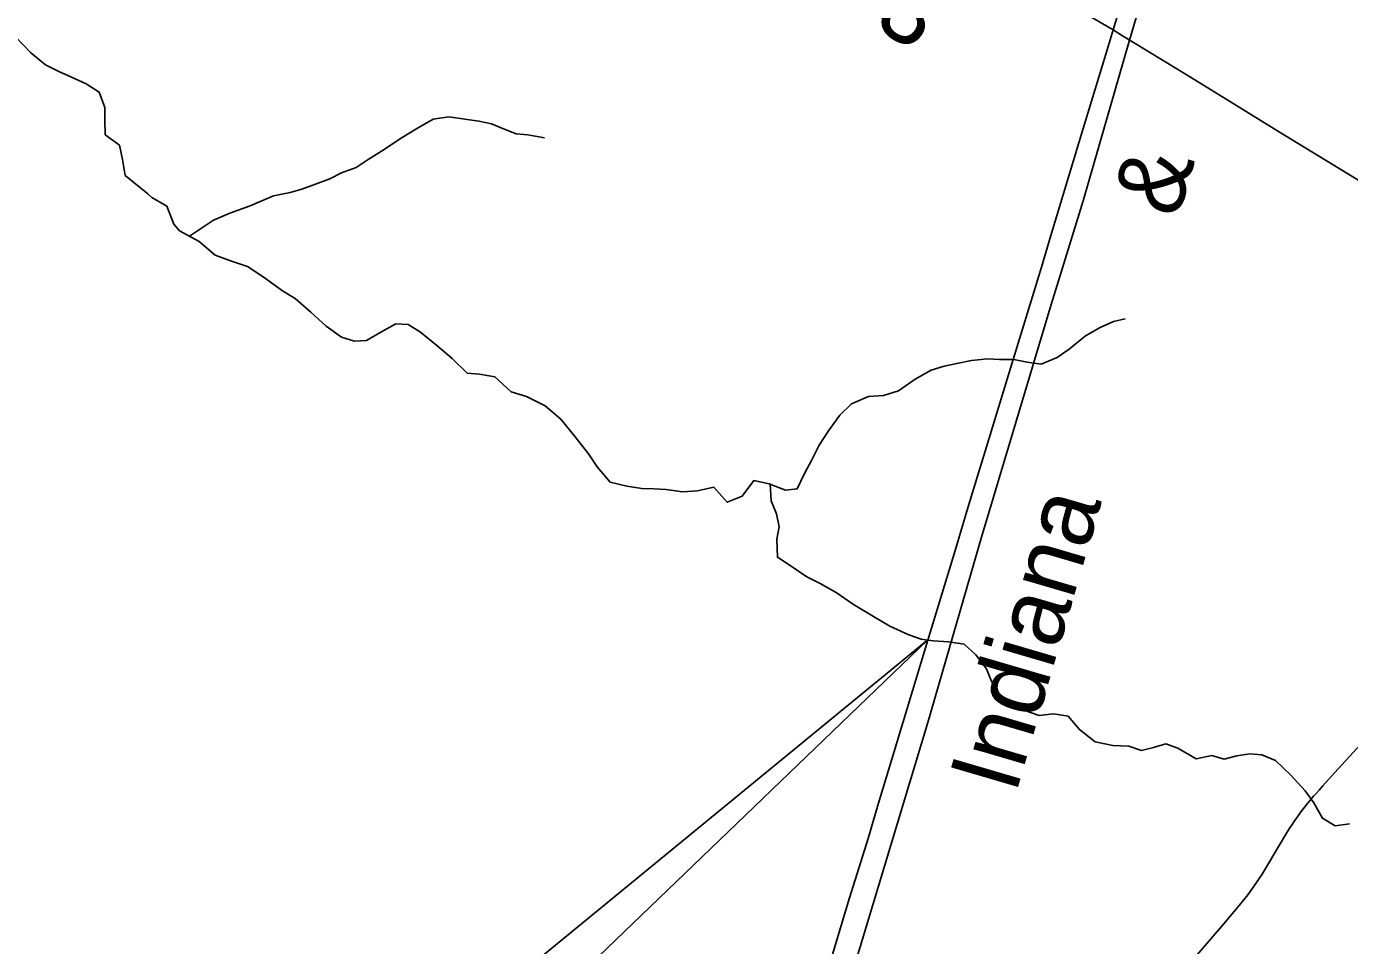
# Model space of a CAD drawing. Extents: x 0 to 34, y 0 to 22.
# Drawn here: x 4.817 to 5.891, y 17.368 to 18.113 of the extents above; entities that cross this region are included whole.
import ezdxf

# ---------------------------------------------------------------- set-up
doc = ezdxf.new("R2010")
doc.units = 0
for name, color, linetype in [('GM_X_County_Road', 7, 'Continuous'), ('GM_X_Minor_River', 7, 'Continuous'), ('GM_X_Rail_Line', 7, 'Continuous'), ('GM_X_Rail_Line_Text', 7, 'Continuous'), ('GM_X_Township_Road', 7, 'Continuous'), ('GM_X_Township_Road_Text', 7, 'Continuous'), ('GM_X_US_Route', 7, 'Continuous'), ('SH_Text', 7, 'Continuous')]:
    doc.layers.add(name, color=color, linetype=linetype)

msp = doc.modelspace()

# ---------------------------------------------------------------- linework, layer by layer
at = {"layer": 'GM_X_County_Road'}
msp.add_lwpolyline([(5.7466, 17.3365), (5.7884, 17.3849), (5.8012, 17.4001), (5.8081, 17.4089), (5.8114, 17.4135), (5.8146, 17.4179), (5.8172, 17.422), (5.8197, 17.4257), (5.8387, 17.4576), (5.8404, 17.4603), (5.8422, 17.4631), (5.8441, 17.466), (5.8455, 17.4681), (5.8475, 17.471), (5.8494, 17.4736), (5.8512, 17.4762), (5.8534, 17.479), (5.8562, 17.4826), (5.8591, 17.486), (5.8615, 17.4888), (5.8635, 17.4911), (5.866, 17.4938), (5.869, 17.4972), (5.8785, 17.5077), (5.9061, 17.5379)], dxfattribs=at)
at = {"layer": 'GM_X_Minor_River'}
for points in [[(4.8023, 18.111), (4.8205, 18.092), (4.8324, 18.0823), (4.8433, 18.0768), (4.8534, 18.0724), (4.8654, 18.0669), (4.8759, 18.0602), (4.8806, 18.0476), (4.8804, 18.0377), (4.8809, 18.0256), (4.8924, 18.017), (4.8949, 18.0056), (4.8969, 17.9926), (4.9154, 17.9775)], [(5.0175, 17.976), (5.0308, 17.9788), (5.0403, 17.9813), (5.0514, 17.9854), (5.0632, 17.9898), (5.0727, 17.9946), (5.0846, 17.9991), (5.0941, 18.0054), (5.1071, 18.0136), (5.1205, 18.0226), (5.1343, 18.0308), (5.1469, 18.0382), (5.1598, 18.04), (5.1841, 18.0367), (5.1943, 18.0343), (5.2041, 18.0304), (5.2143, 18.0264), (5.2238, 18.0256), (5.2374, 18.0231)], [(4.9154, 17.9775), (4.9188, 17.9746), (4.9308, 17.9676), (4.9364, 17.953), (4.9412, 17.9475)], [(4.9492, 17.9432), (4.9686, 17.9563), (4.982, 17.9618), (4.9984, 17.968), (5.0175, 17.976)], [(4.9412, 17.9475), (4.957, 17.939), (4.9701, 17.9278), (4.9833, 17.9231), (4.9962, 17.9187), (5.009, 17.9102), (5.0248, 17.899), (5.035, 17.8928), (5.0477, 17.8816), (5.0601, 17.8701), (5.0725, 17.8612), (5.0831, 17.858), (5.093, 17.8586), (5.1045, 17.8653), (5.1167, 17.872), (5.1266, 17.8715), (5.1368, 17.8653), (5.1499, 17.8545), (5.1623, 17.8441), (5.1747, 17.8321), (5.1846, 17.8312), (5.1971, 17.8292), (5.2102, 17.8169), (5.2227, 17.8133), (5.2378, 17.8055), (5.2505, 17.7947), (5.2621, 17.7805), (5.273, 17.7667), (5.28, 17.756), (5.2905, 17.7437), (5.3041, 17.7405), (5.3162, 17.7384), (5.3261, 17.7383), (5.336, 17.7378), (5.3493, 17.7357), (5.3614, 17.7367), (5.3748, 17.7396), (5.3856, 17.7273), (5.3978, 17.7324), (5.4071, 17.7449), (5.4196, 17.7424), (5.4328, 17.7373), (5.4424, 17.7383), (5.4482, 17.7508), (5.4541, 17.7613), (5.4603, 17.7738), (5.4677, 17.7854), (5.477, 17.7979), (5.4866, 17.8072), (5.5003, 17.8131), (5.5125, 17.8141), (5.5247, 17.8177), (5.5381, 17.8271), (5.5511, 17.8345), (5.5618, 17.8378), (5.5732, 17.8403), (5.5839, 17.8424), (5.5968, 17.8438), (5.6067, 17.8432), (5.6181, 17.8431), (5.6291, 17.8411), (5.6405, 17.8394), (5.6535, 17.8449), (5.663, 17.8516), (5.6765, 17.8625), (5.6883, 17.8691), (5.699, 17.8739), (5.7086, 17.8761)], [(5.4204, 17.7421), (5.4213, 17.7284), (5.4257, 17.718), (5.4279, 17.7074), (5.4258, 17.6975), (5.4264, 17.6827), (5.4366, 17.6761), (5.4501, 17.6669), (5.4611, 17.6614), (5.4739, 17.654), (5.4882, 17.6444), (5.5044, 17.6347), (5.5176, 17.6269), (5.5331, 17.6199), (5.5429, 17.6163), (5.5527, 17.615), (5.5653, 17.6141), (5.5778, 17.6121), (5.5875, 17.6036), (5.5961, 17.5921), (5.5998, 17.5826), (5.6053, 17.573), (5.6166, 17.5626), (5.6264, 17.5587), (5.6389, 17.5543), (5.6503, 17.5557), (5.6624, 17.5537), (5.6714, 17.5429), (5.6842, 17.5329), (5.6986, 17.53), (5.7115, 17.5295), (5.7217, 17.5259), (5.7316, 17.5285), (5.7415, 17.5314), (5.7514, 17.5278), (5.7661, 17.5193), (5.779, 17.5218), (5.7888, 17.519), (5.7991, 17.5215), (5.8098, 17.5233), (5.8196, 17.5224), (5.8306, 17.5177), (5.843, 17.5058), (5.8546, 17.4931), (5.8617, 17.4835), (5.8687, 17.4709), (5.8789, 17.4647), (5.8907, 17.4664)]]:
    msp.add_lwpolyline(points, dxfattribs=at)
at = {"layer": 'GM_X_Rail_Line'}
msp.add_lwpolyline([(5.4635, 17.2672), (5.5484, 17.5486), (5.592, 17.6989), (5.6477, 17.885), (5.6745, 17.972), (5.7122, 18.1022), (5.7335, 18.1748), (5.748, 18.2243), (5.7604, 18.268), (5.7702, 18.3157), (5.7789, 18.3584), (5.7833, 18.3885), (5.7877, 18.43), (5.7896, 18.4598), (5.7906, 18.4836), (5.7921, 18.5466), (5.7944, 18.6863), (5.7957, 18.7861), (5.7992, 18.985), (5.7999, 19.0268), (5.8013, 19.056), (5.8049, 19.0904), (5.8078, 19.1192)], dxfattribs=at)
at = {"layer": 'GM_X_Township_Road'}
for points in [[(5.6989, 18.1106), (5.6755, 18.1241)], [(6.1434, 17.8386), (6.1386, 17.8417), (6.1323, 17.8458), (6.0938, 17.8698), (6.0226, 17.9129), (5.9896, 17.9328), (5.9668, 17.9467), (5.928, 17.9702), (5.833, 18.0281), (5.7977, 18.0502), (5.7616, 18.0722), (5.7181, 18.0987), (5.7065, 18.1059), (5.6989, 18.1106)]]:
    msp.add_lwpolyline(points, dxfattribs=at)
at = {"layer": 'GM_X_US_Route'}
msp.add_lwpolyline([(5.4699, 17.357), (5.4849, 17.4063), (5.4999, 17.4544), (5.5081, 17.4824), (5.521, 17.5252), (5.5464, 17.6091), (5.5706, 17.6881), (5.5818, 17.7256), (5.599, 17.7821), (5.6165, 17.8397), (5.6406, 17.9181), (5.6482, 17.9438), (5.6745, 18.0306), (5.6949, 18.0971), (5.6989, 18.1106), (5.7141, 18.1608)], dxfattribs=at)
at = {"layer": 'SH_Text'}
msp.add_lwpolyline([(3.596, 17.0143), (4.7456, 17.0143), (4.7456, 16.9576), (5.5484, 17.6156), (4.7456, 16.844), (4.7456, 16.7873), (3.596, 16.7873)], close=True, dxfattribs=at)

# ---------------------------------------------------------------- texts
at = {"layer": 'GM_X_Rail_Line_Text'}
for s, height, rotation, p in [('&', 0.0566, 73.6849, (5.7512, 17.9567)), ('Indiana', 0.05663, 73.6578, (5.6197, 17.4896))]:
    msp.add_text(s, height=height, rotation=rotation, dxfattribs=at).set_placement(p)
at = {"layer": 'GM_X_Township_Road_Text'}
msp.add_text('3', height=0.0568, rotation=328.9479, dxfattribs=at).set_placement((5.5027, 18.1141))

doc.saveas('drawing.dxf')
